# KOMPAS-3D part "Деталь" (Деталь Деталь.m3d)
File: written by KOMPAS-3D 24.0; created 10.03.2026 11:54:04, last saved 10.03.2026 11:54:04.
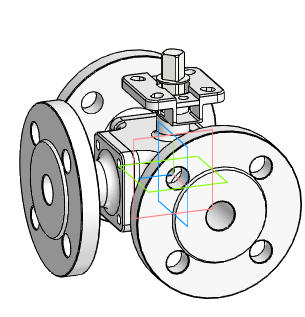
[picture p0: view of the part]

Document properties: Автор: R2D2; Полное имя файла: E:\Работа\Зайцев\BV3232P(4pc)-FP-3WL-F-ISO-H Кран шаровой DN.ru Ду15-100 Ру16\DN20\исходные материалы\Деталь Деталь.m3d

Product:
- Body: Твердое тело1  | qty 1
- Part/product: Деталь
    additional columns: Типовые

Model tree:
1. Твердое тело1  (labels: Твердое тело1)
